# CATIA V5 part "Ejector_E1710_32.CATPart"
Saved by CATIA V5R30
Part number: Vyhazovac_7x160_8
Nomenclature: E1710/7x160
Description: MEUSBURGER
Property "Material": "1.221"
Publications: "__DrillHole", "Base"
Bounding box of the stored display mesh (mm): x -5.992 to 5.992, y -5.992 to 5.992, z 0 to 152
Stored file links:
  E:\Bakalarka\Model\Forma_v7\Ejector_E1710_32.CATPart
  E:\dev\MoldDesign\intel_a\startup\components\MoldCatalog\Ejector\Meusburger\Ejector_E1710\TableE1710.txt
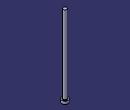
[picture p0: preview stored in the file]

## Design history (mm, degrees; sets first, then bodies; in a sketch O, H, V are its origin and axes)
Parameters
  Ref = "E1710/7x160" {design table}
  D1 = 7 mm {design table}
  D3 = 12 mm {design table}
  L = 160 mm {design table}
  L3 = 5 mm {design table}
  R = 0.5 mm {design table}
  k_d3 = 13 mm {design table}
  k_d1 = 7.2 mm {design table}
  k_F = 0.5 mm {design table}
  kl = 17 mm {design table}
  Mat = "1.221" {design table}
  HeatTreat = "ISO6751" {design table}
  Offset_Parting = 10 mm
  Anti_Rotation = "Normal"
  Anti_Rotation_D = 4 mm
  Anti_Rotation_D_Icut = 4 mm
  Add_Length_L = 1.3377 mm
  Add_Length_D3 = 0 mm
  SupplierRef = "Meusburger 2017"
  BmpRef = "F_MldEjectorD1"
  DrillHole_Length = 225 mm
  ValidationTest = false
  Anti_Rotation_D_min = 4 mm {= OffSet_D1 /2}
  Anti_Rotation_D_max = 5.925 mm {= D3/2-0.075mm}
  Anti_Rotation_D_ref = 4 mm {= Anti_Rotation_D}
  Anti_Rotation_D_Icut_ref = 4 mm {= Anti_Rotation_D_Icut}
  Anti_Rotation_Ref_Icut = 2.3246 mm
  Offset_L = 20 mm
  D = 7 mm {= D1}
  OffSet_D1 = 8 mm {= D1+2*R}
  OffSet_D3 = 13 mm {= D3+1mm}
  XG_Split = 72 mm
  YG_Split = 20 mm
  ZG_Split = -198 mm
  DirX_Split = 0 mm
  DirY_Split = 0 mm
  DirZ_Split = 1 mm
Set1 "BaseBody"
  Point1 "Base": (0, 0, 0)
  Plane1: type Offset, RefPlane xy-plane, Offset 225 {= DrillHole_Length}, reversed
  Sketch1 "Sketch.2" on xy-plane, origin (0, 0, 0), H (1, 0, 0), V (0, 1, 0)
    point P1 (-0.46, 1.1623)
    point P2 (0.46, 1.1623)
    construction line L1 (-0.46, 1.1623) -> (0.46, 1.1623)
    point P3 (0.46, -1.1623)
    line L2 (0.46, -1.1623) -> (0.46, 1.1623)
    point P4 (-0.46, -1.1623)
    construction line L3 (0.46, -1.1623) -> (-0.46, -1.1623)
    line L4 (-0.46, 1.1623) -> (-0.46, -1.1623)
    point P5 (-0.21, 1.1623)
    arc A1 centre (-0.21, 1.1623) radius 0.25 from (-0.21, 1.4123) to (-0.46, 1.1623) ccw
    point P7 (0.21, 1.1623)
    point P8 (0.21, 1.4123)
    arc A2 centre (0.21, 1.1623) radius 0.25 from (0.46, 1.1623) to (0.21, 1.4123) ccw
    line L5 (-0.21, 1.4123) -> (0.21, 1.4123)
    point P9 (-0.46, -1.1623)
    arc A3 centre (-0.21, -1.1623) radius 0.25 from (-0.46, -1.1623) to (-0.21, -1.4123) ccw
    point P11 (0.21, -1.4123)
    line L6 (-0.21, -1.4123) -> (0.21, -1.4123)
    point P12 (0.46, -1.1623)
    arc A4 centre (0.21, -1.1623) radius 0.25 from (0.21, -1.4123) to (0.46, -1.1623) ccw
    point P14 (-0.46, 1.1623)
    point P15 (-0.46, -1.1623)
    point P16 (0.46, 1.1623)
    point P17 (0.46, -1.1623)
    reference projected circle E1 centre (0, 0) radius 1.25 from edge [face of Shaft1 from Sketch2.L3 | face of Shaft1 from Sketch2.L4]
    reference projected circle E2 centre (0, 0) radius 1.25 from edge [face of Shaft1 from Sketch2.L3 | face of Shaft1 from Sketch2.L4]
    reference projected circle E3 centre (0, 0) radius 1.25 from edge [face of Shaft1 from Sketch2.L3 | face of Shaft1 from Sketch2.L4]
    reference projected circle E4 centre (0, 0) radius 1.25 from edge [face of Shaft1 from Sketch2.L3 | face of Shaft1 from Sketch2.L4]
    point P18 (-0.46, -1.1623)
    point P19 (-0.21, -1.4123)
    point P20 (0.21, -1.4123)
    point P21 (0.46, -1.1623)
    point P22 (-0.21, -1.4123)
    point P23 (0.21, -1.4123)
    distance P14 P15 = 2.3246 (reference)
    distance P16 P17 = 2.3246 (reference)
    distance L1 P14 = 0 (reference)
    radius A1 = 3.5
    distance L4 V = 4.01
    distance L2 V = 5.935
    distance L5 L6 = 12
    horizontal: L1 H, L3 H, L5 H
    vertical: L2 V, L4 V
    coincidence: P5 L1, P7 L1, P3 P12, P14 L4, P15 L4, P16 L2, P17 L2, P14 E1, P15 E2, P16 E3, P17 E4, P3 P21, P4 P18, P20 P23, P19 P22
    tangency: A1 L4, A2 L2, A2 L5, A1 L5
    symmetry: P1 P9 H, A1 A3 H, P8 P11 H, L5 L6 H, P2 P12 H, A2 A4 H
  DatumSurface1
Body1 "PartBody" (main body)
  Sketch2 "Sketch.1" on zx-plane, origin (0, 0, 0), H (-1, 0, 0), V (0, 0, 1)
    point P1 (0, 160)
    line L1 (3.5, 160) -> (0, 160)
    line L2 (3.5, 5) -> (3.5, 160)
    line L3 (6, 5) -> (3.5, 5)
    line L4 (6, 0) -> (6, 5)
    point P5 (0, 0)
    line L5 (0, 0) -> (6, 0)
    point P6 (0, 160)
    axis line L6 (0, 160) -> (0, 0)
    point P7 (0, 0)
    point P8 (3.5, 5)
    point P9 (3.5, 5)
    line L7 (0, 160) -> (0, 0)
    distance L5 L3 = 5 {= L3}
    distance L5 L1 = 160 {= L}
    distance L2 L6 = 3.5 {= D1 /2}
    distance L4 L6 = 6 {= D3 /2}
    coincidence: L6 P5, P1 L6, L5 H, L6 V, P7 O, P6 P1, P8 P9
    vertical: L2 V, L7 V
    horizontal: L1 H
  Shaft1 "Shaft.1": profile Sketch2, axis Sketch2.L6, angle 360
  Pocket1 "Pocket.1": profile Sketch1, direction (0, 0, 1), length 6, outer side, deactivated
  Pocket2 "Pocket.2": profile Sketch1, direction (0, 0, 1), length 6, outer side, deactivated
  Fillet1: radius 0.5 {= R}, on edge [face of Shaft1 from Sketch2.L2 | face of Shaft1 from Sketch2.L3]
  Pocket3: profile face of Shaft1 from Sketch2.L1, direction along face of Shaft1 from Sketch2.L1 reversed, up to face of DatumSurface1
Body2 "__DrillHole"
  Sketch3 "Sketch.3" on face of Shaft1, origin (0, 0, 0), H (1, 0, 0), V (0, -1, 0)
    point P1 (0, 0)
    reference projected point E1 (0, 0) from Point1
    coincidence: E1 P1
  Hole1 "Hole.1": placed by Sketch3, at (0, 0, 0) direction (0, 0, 1), diameter 8 {= OffSet_D1}, depth 140 {= L-Offset_L}
  Sketch4 "Sketch.4" on face of Shaft1, origin (0, 0, 0), H (1, 0, 0), V (0, -1, 0)
    point P1 (0, 0)
    reference projected point E1 (0, 0) from Point1
    coincidence: E1 P1
  Hole2 "Hole.2": placed by Sketch4, at (0, 0, 0) direction (0, 0, 1), diameter 7 {= D1}, depth 160 {= L}
  Sketch5 "Sketch.5" on face of Shaft1 from Sketch2.L3, origin (0, 0, 5), H (1, 0, 0), V (0, 1, 0)
    point P1 (0, 0)
    reference projected point E1 (0, 0) from Point1
    coincidence: E1 P1
  Hole3 "Hole.3": placed by Sketch5, at (0, 0, 5) direction (0, 0, -1), diameter 13 {= OffSet_D3}, depth 230 {= L3 +DrillHole_Length}
  Chamfer1: length 0.5 {= k_F}, angle 45, on edge [face of Hole1 | face of Hole3]
  Body3 "__Body.1"
    Pocket4 "Pocket.3": profile Sketch1, direction (0, 0, -1), length 225, opposite side length 5, deactivated
  Assemble1: tool Body3
  Chamfer2: length 0.5 {= k_F}, angle 45, on edge [start face of Pocket4 | face of Hole1], deactivated
  Body4 "__Body.2"
    Pocket5 "Pocket.4": profile Sketch1, direction (0, 0, -1), length 225, opposite side length 5, deactivated
  Assemble2: tool Body4
  Chamfer3: length 0.5 {= k_F}, angle 45, on edge [start face of Pocket5 | face of Hole1], deactivated
Relations
  design table "TableE1710", configuration 278, drives Ref, D1, D3, L, L3, R, k_d3, k_d1, k_F, kl, Mat, HeatTreat
  Offset_L = 20mm (deactivated)
  rule "Cut_Head_rule":
    let sketch_cut (length)
    let PartBody_Pocket_Sketch (Boolean)
    let I_PartBody_Pocket (Boolean)
    let D_PartBody_Pocket (Boolean)
    let N_DrillHole_Hole (Boolean)
    let N_DrillHole_Hole_Sketch (Boolean)
    let I_DrillHole_Pocket (Boolean)
    let D_DrillHole_Pocket (Boolean)
    /* --------------------------------------------------------------------------------------*/
    if Anti_Rotation =="Normal"
    {
    	sketch_cut=Anti_Rotation_D_max
    	PartBody_Pocket_Sketch = false
    	I_PartBody_Pocket = false
    	D_PartBody_Pocket = false
    	N_DrillHole_Hole = true
    	N_DrillHole_Hole_Sketch = true
    	I_DrillHole_Pocket = false
    	D_DrillHole_Pocket = false
    	Chamfer1.Activity= true
    	Chamfer2.Activity= false
    	Chamfer3.Activity= false
    }
    if Anti_Rotation == "I_Cut"
    {
    	sketch_cut=Anti_Rotation_D_Icut_ref
    	PartBody_Pocket_Sketch = true
    	I_PartBody_Pocket = true
    	D_PartBody_Pocket = false
    	N_DrillHole_Hole = false
    	N_DrillHole_Hole_Sketch = false
    	I_DrillHole_Pocket = true
    	D_DrillHole_Pocket = false
    	Chamfer1.Activity= false
    	Chamfer2.Activity= true
    	Chamfer3.Activity= false
    }
    if Anti_Rotation =="D_Cut"
    {
    	sketch_cut=Anti_Rotation_D_max
    	PartBody_Pocket_Sketch = true
    	I_PartBody_Pocket = false
    	D_PartBody_Pocket = true
    	N_DrillHole_Hole = false
    	N_DrillHole_Hole_Sketch = false
    	I_DrillHole_Pocket = false
    	D_DrillHole_Pocket = true
    	Chamfer1.Activity= false
    	Chamfer2.Activity= false
    	Chamfer3.Activity= true
    }
    /* --------------------------------------------------------------------------------------*/
    Sketch1.distance(L2 V) = sketch_cut+0.01mm
    Sketch1.distance(L4 V) =Anti_Rotation_D_ref+0.01mm
    Sketch1.radius(A1) =D/2
    Pocket4.FirstLimit.Depth = DrillHole_Length
    Pocket5.FirstLimit.Depth = DrillHole_Length
    Pocket1.FirstLimit.Depth = L3+1mm
    Pocket2.FirstLimit.Depth = L3+1mm
    Pocket4.SecondLimit.Depth = L3
    Pocket5.SecondLimit.Depth =L3
    Pocket1.Activity = I_PartBody_Pocket
    Pocket2.Activity = D_PartBody_Pocket
    Sketch1.Activity =PartBody_Pocket_Sketch
    Hole3.Activity= N_DrillHole_Hole
    Sketch5.Activity = N_DrillHole_Hole_Sketch
    Pocket4.Activity = I_DrillHole_Pocket
    Pocket5.Activity  = D_DrillHole_Pocket
  rule "Anti_Rotation_Icut_constrain":
    let Ref1(length)
    let Ref2(length)
    let Ref3(length)
    let Diam1(length)
    let Diam2(length)
    let Add_Length_Lmin (length)
    Ref1=Sketch1.distance(P14 P15)
    Ref2=Sketch1.distance(P16 P17)
    Diam1=D
    Diam2=D3
    /* --------------------------------------------------------------------*/
    if Ref1 >Ref2
    	Anti_Rotation_Ref_Icut = Ref1
    else
    	Anti_Rotation_Ref_Icut  =Ref2
    Add_Length_D3 .InferiorRange=Anti_Rotation_Ref_Icut /2+Diam1/2 -Diam2/2
    if Add_Length_D3 .InferiorRange<0mm
    	Add_Length_D3 .InferiorRange=0mm
    if ValidationTest == "true"
    	Ref3   = 2*Add_Length_L +Anti_Rotation_Ref_Icut  +2*Diam1/2
    else
    	Ref3  =Diam2+2*Add_Length_D3
    if Ref3 <Diam2
    {
    	Ref3 =Diam2
    }
    /* --------------------------------------------------------------------*/
    Sketch1.distance(L5 L6) = Ref3
    Add_Length_L .InferiorRange=Diam2/2-Anti_Rotation_Ref_Icut/2-Diam1/2
    Add_Length_Lmin=Diam2/2-Anti_Rotation_Ref_Icut/2-Diam1/2
    if Add_Length_Lmin<0mm
    	Add_Length_L .InferiorRange=0mm
    else
    	Add_Length_L .InferiorRange=Add_Length_Lmin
